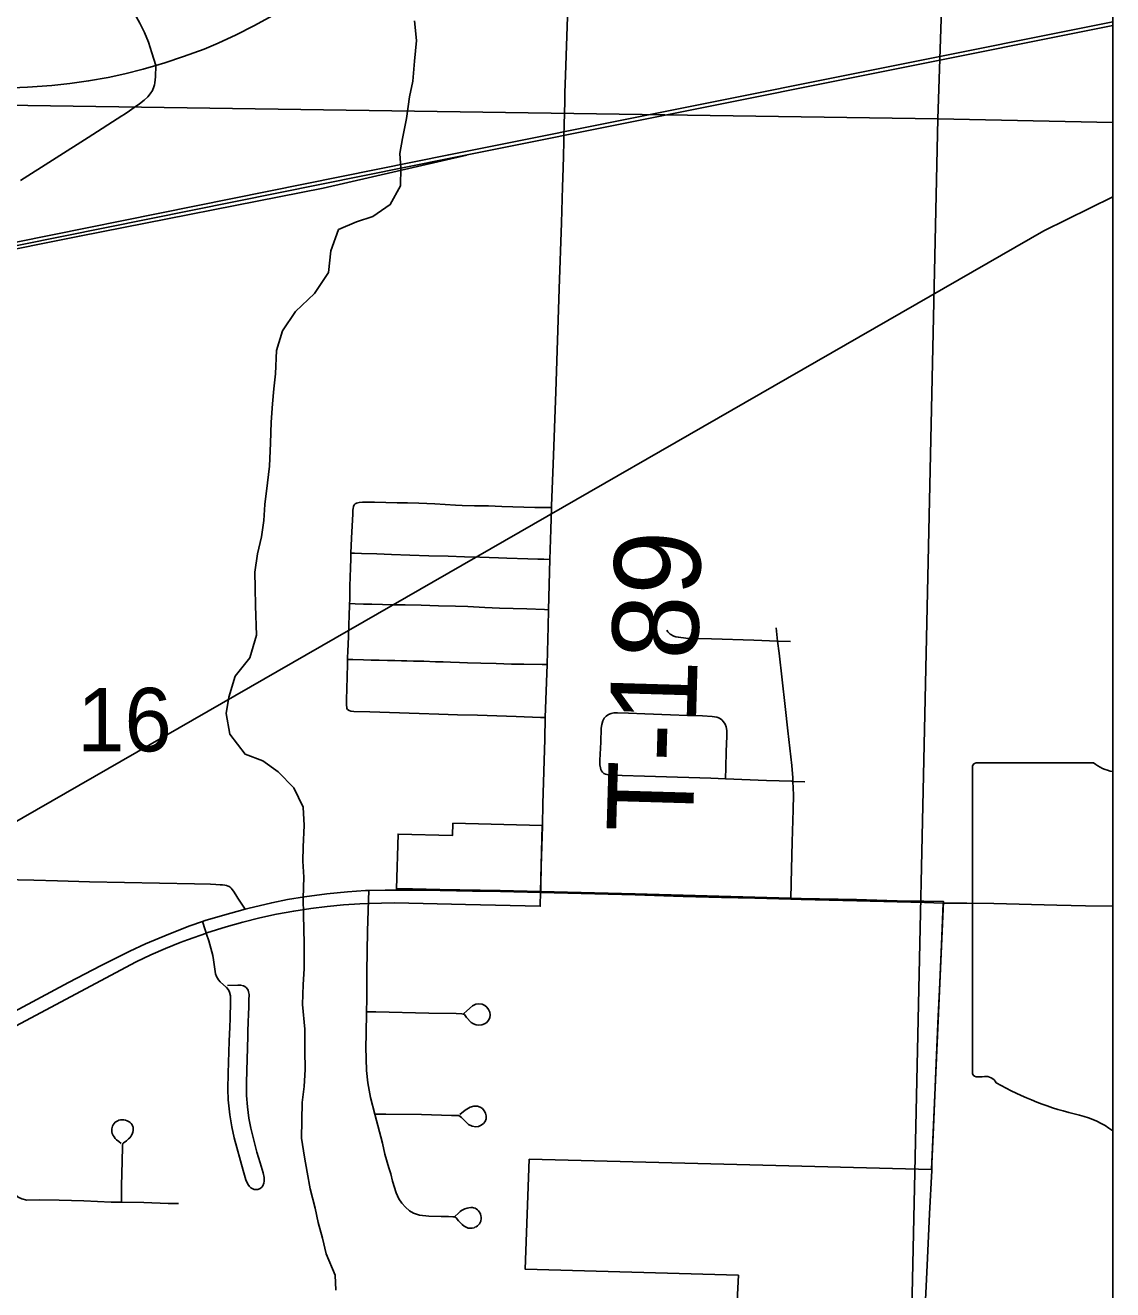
# Model space of a CAD drawing. Extents: x 0 to 34, y 0 to 22.
# Drawn here: x 8.183 to 8.9, y 17.76 to 18.594 of the extents above; entities that cross this region are included whole.
import ezdxf

# ---------------------------------------------------------------- set-up
doc = ezdxf.new("R2010")
doc.units = 0
for name, color, linetype in [('GM_X_City_Street', 7, 'Continuous'), ('GM_X_Corporation', 7, 'Continuous'), ('GM_X_County_Road', 7, 'Continuous'), ('GM_X_Minor_River', 7, 'Continuous'), ('GM_X_Rail_Line', 7, 'Continuous'), ('GM_X_Section_Text', 7, 'Continuous'), ('GM_X_State_Route', 7, 'Continuous'), ('GM_X_Township_Road', 7, 'Continuous'), ('GM_X_Township_Road_Text', 7, 'Continuous'), ('GM_X_Unincorporated_Text', 7, 'Continuous'), ('GM_X_US_Route', 7, 'Continuous'), ('SH_Data', 7, 'Continuous')]:
    doc.layers.add(name, color=color, linetype=linetype)

msp = doc.modelspace()

# ---------------------------------------------------------------- linework, layer by layer
at = {"layer": 'GM_X_City_Street'}
for points in [[(8.43372, 17.81455), (8.43131, 17.81714), (8.42944, 17.82018), (8.42776, 17.82405), (8.42532, 17.83165), (8.42423, 17.83647), (8.42276, 17.84056), (8.42023, 17.84949), (8.4186, 17.85682), (8.41367, 17.87598), (8.41085, 17.88694), (8.40894, 17.89662), (8.40809, 17.90457), (8.40758, 17.92002), (8.40779, 17.9287), (8.40809, 17.94344), (8.40827, 17.95169), (8.40844, 17.96973), (8.40881, 17.99644), (8.40945, 18.01691), (8.40965, 18.02327)], [(8.31658, 17.96078), (8.32323, 17.96098), (8.3251, 17.96093), (8.32693, 17.9605), (8.32802, 17.95993), (8.32895, 17.95917), (8.33004, 17.95769), (8.33043, 17.95654), (8.33072, 17.9547), (8.33061, 17.951), (8.33046, 17.94608), (8.33025, 17.94226), (8.33002, 17.93604), (8.32994, 17.93113), (8.32981, 17.92921), (8.32979, 17.92736), (8.32904, 17.89685), (8.32912, 17.88815), (8.3297, 17.88072), (8.33064, 17.87332), (8.33192, 17.8666), (8.33586, 17.85093), (8.338, 17.84378), (8.34005, 17.83722), (8.34063, 17.83414), (8.34069, 17.83165), (8.34046, 17.83043), (8.33979, 17.82874), (8.33902, 17.82777), (8.33813, 17.82699), (8.33647, 17.82624), (8.33405, 17.82629), (8.33189, 17.82743), (8.33103, 17.82829), (8.32993, 17.82982), (8.32866, 17.83269), (8.32685, 17.83869), (8.32088, 17.86027), (8.31931, 17.86756), (8.31809, 17.87555), (8.31704, 17.88544), (8.31678, 17.89227), (8.31702, 17.90284), (8.31755, 17.92397), (8.31812, 17.93328), (8.31833, 17.93887), (8.31856, 17.95008), (8.3184, 17.95381), (8.31786, 17.95621), (8.31708, 17.95788), (8.31594, 17.95933), (8.31174, 17.96306), (8.31054, 17.96448), (8.30927, 17.96659), (8.30867, 17.96834), (8.30732, 17.97764), (8.30675, 17.98053), (8.30547, 17.98539), (8.30408, 17.99024), (8.30268, 17.99456), (8.30176, 17.9974), (8.3, 18.00284)], [(8.40809, 17.94344), (8.41424, 17.94329), (8.44928, 17.94247), (8.4673, 17.94225), (8.47091, 17.94201), (8.47206, 17.94184), (8.47269, 17.9415), (8.47312, 17.94102), (8.47411, 17.93963), (8.47709, 17.9364), (8.47866, 17.93542), (8.48039, 17.93478), (8.48222, 17.93453), (8.48407, 17.9347), (8.48582, 17.93535), (8.48736, 17.93639), (8.48857, 17.9378), (8.48933, 17.93947), (8.48958, 17.9413), (8.48933, 17.94314), (8.48863, 17.94487), (8.48753, 17.94638), (8.48612, 17.9476), (8.48445, 17.94841), (8.48202, 17.9487), (8.4802, 17.94835), (8.47797, 17.94722), (8.47419, 17.9439), (8.47229, 17.94219)], [(8.41367, 17.87598), (8.42079, 17.8759), (8.44433, 17.87565), (8.46415, 17.87506), (8.46696, 17.8751), (8.46902, 17.87502), (8.47074, 17.87379), (8.47544, 17.86902), (8.47771, 17.86802), (8.48013, 17.8676), (8.48197, 17.86783), (8.48368, 17.86854), (8.48514, 17.86968), (8.48625, 17.87117), (8.48691, 17.87289), (8.48703, 17.87473), (8.48661, 17.87653), (8.48577, 17.87819), (8.48455, 17.87959), (8.48302, 17.88061), (8.48125, 17.88115), (8.47879, 17.88117), (8.4764, 17.88052), (8.47321, 17.8786), (8.46959, 17.8756)], [(8.24653, 17.81786), (8.24653, 17.82109), (8.24652, 17.8289), (8.24693, 17.83647), (8.24724, 17.85391), (8.24733, 17.85545), (8.2476, 17.85648), (8.24804, 17.85695), (8.249, 17.85771), (8.24983, 17.85838), (8.25126, 17.85958), (8.25201, 17.86029), (8.25283, 17.86124), (8.25328, 17.86204), (8.2536, 17.86272), (8.25406, 17.86411), (8.25427, 17.86514), (8.25431, 17.86625), (8.25423, 17.86729), (8.25397, 17.86823), (8.25359, 17.86895), (8.25299, 17.86971), (8.25224, 17.87035), (8.25167, 17.87077), (8.25027, 17.87159), (8.24926, 17.87189), (8.24813, 17.87209), (8.24704, 17.87217), (8.24591, 17.87209), (8.24493, 17.87192), (8.2441, 17.87159), (8.24326, 17.87113), (8.24254, 17.8706), (8.24179, 17.86978), (8.24116, 17.8689), (8.24074, 17.86798), (8.24045, 17.8672), (8.24026, 17.86619), (8.24025, 17.86521), (8.24032, 17.86431), (8.24057, 17.86322), (8.24112, 17.86194), (8.24172, 17.86088), (8.24253, 17.85992), (8.24335, 17.85909), (8.24482, 17.85786), (8.2465, 17.85662)], [(8.17665, 17.82278), (8.17846, 17.8213), (8.18093, 17.81999), (8.18414, 17.81933), (8.19243, 17.81935), (8.20548, 17.81916), (8.22177, 17.81868), (8.2397, 17.81796), (8.24653, 17.81786), (8.26142, 17.81765), (8.27735, 17.81711), (8.28412, 17.81701)], [(8.43372, 17.81455), (8.43639, 17.81228), (8.4391, 17.81063), (8.44299, 17.80932), (8.44916, 17.80857), (8.45726, 17.80838), (8.46224, 17.80836), (8.46502, 17.80831), (8.46593, 17.8083), (8.46667, 17.80807), (8.46733, 17.80749), (8.46886, 17.80551), (8.47109, 17.80327), (8.47255, 17.80203), (8.47418, 17.80115), (8.47512, 17.80085), (8.47598, 17.80073), (8.47783, 17.80082), (8.47899, 17.80109), (8.47962, 17.80137), (8.48048, 17.80174), (8.48122, 17.80233), (8.48251, 17.80366), (8.48338, 17.80531), (8.48373, 17.80713), (8.48375, 17.8081), (8.48359, 17.80899), (8.48335, 17.80994), (8.48297, 17.81075), (8.48241, 17.81163), (8.48192, 17.81228), (8.48131, 17.81286), (8.48047, 17.81343), (8.47967, 17.81386), (8.47875, 17.81414), (8.47788, 17.8143), (8.47691, 17.81437), (8.4756, 17.81425), (8.47445, 17.81403), (8.47287, 17.8134), (8.47158, 17.81283), (8.47071, 17.81234), (8.46989, 17.81176), (8.46865, 17.81067), (8.46644, 17.8085)]]:
    msp.add_lwpolyline(points, dxfattribs=at)
at = {"layer": 'GM_X_Corporation'}
for points in [[(8.9, 14.49422), (8.9, 20.89996), (2.1, 20.89996)], [(8.9, 14.49422), (8.9, 20.50415)], [(8.6425, 17.55961), (8.65329, 17.76979), (8.51264, 17.77379), (8.51539, 17.84616), (8.78059, 17.83951), (8.78854, 18.01597), (8.77547, 18.01629), (8.75791, 18.01656), (8.7312, 18.01732), (8.69467, 18.01802), (8.68782, 18.01822), (8.66408, 18.01894), (8.61684, 18.02016), (8.58516, 18.02109), (8.5229, 18.02261), (8.52397, 18.06619), (8.46513, 18.06759), (8.46488, 18.05964), (8.42888, 18.06053), (8.4278, 18.02432), (8.43847, 18.02433), (8.45651, 18.02403), (8.49629, 18.02326), (8.52288, 18.02261), (8.52268, 18.0129), (8.47331, 18.0141), (8.42679, 18.01515), (8.40929, 18.01482), (8.40363, 18.01459), (8.39285, 18.01384), (8.3821, 18.01279), (8.37139, 18.01144), (8.36011, 18.0097), (8.34889, 18.00762), (8.33774, 18.0052), (8.32666, 18.00246), (8.31567, 17.99939), (8.30282, 17.99536), (8.30261, 17.99528), (8.29012, 17.99088), (8.28526, 17.98903), (8.27557, 17.98512), (8.26599, 17.98095), (8.25627, 17.97639), (8.17353, 17.93211)]]:
    msp.add_lwpolyline(points, dxfattribs=at)
for points in [[(8.81843, 19.53953), (8.78463, 18.5318), (7.73457, 18.54715), (7.75042, 19.56547)], [(8.9, 18.52947), (8.9, 19.53779), (8.81843, 19.53953), (8.78463, 18.5318)], [(7.73457, 18.54715), (8.78463, 18.5318), (8.76248, 17.51563), (7.70158, 17.53728)], [(8.9, 17.51187), (8.9, 18.52947), (8.78463, 18.5318), (8.76248, 17.51563)]]:
    msp.add_lwpolyline(points, close=True, dxfattribs=at)
at = {"layer": 'GM_X_County_Road'}
msp.add_lwpolyline([(8.18012, 18.49132), (8.22474, 18.51963), (8.24677, 18.53378), (8.24833, 18.53481), (8.25193, 18.53724), (8.25498, 18.53935), (8.25859, 18.54182), (8.26162, 18.54413), (8.26395, 18.54635), (8.26559, 18.54836), (8.26695, 18.5506), (8.26795, 18.55302), (8.2683, 18.55429), (8.26854, 18.5556), (8.26896, 18.55958), (8.26935, 18.5671)], dxfattribs=at)
at = {"layer": 'GM_X_Minor_River'}
msp.add_lwpolyline([(8.38799, 17.75987), (8.38742, 17.76975), (8.38163, 17.7839), (8.37917, 17.79419), (8.37633, 17.8045), (8.37424, 17.81403), (8.37107, 17.82661), (8.36901, 17.83766), (8.36731, 17.84756), (8.36527, 17.86012), (8.36573, 17.88364), (8.36707, 17.89424), (8.36766, 17.90524), (8.36752, 17.91777), (8.36742, 17.93181), (8.36584, 17.94816), (8.36647, 17.96143), (8.36705, 17.97167), (8.36699, 17.98837), (8.3668, 17.99786), (8.3666, 18.00735), (8.36643, 18.01836), (8.3667, 18.03202), (8.36615, 18.04266), (8.36633, 18.05214), (8.36698, 18.06617), (8.36645, 18.07832), (8.36025, 18.09097), (8.34984, 18.10142), (8.33974, 18.10882), (8.32807, 18.11322), (8.31808, 18.12632), (8.31569, 18.14003), (8.31741, 18.15062), (8.32148, 18.16459), (8.33119, 18.17655), (8.33565, 18.19164), (8.33489, 18.21101), (8.33473, 18.22278), (8.33455, 18.23303), (8.3363, 18.24514), (8.3388, 18.25648), (8.34052, 18.26707), (8.3411, 18.27769), (8.3429, 18.29207), (8.34425, 18.30305), (8.34492, 18.31822), (8.34519, 18.33188), (8.34618, 18.34401), (8.34713, 18.35386), (8.34808, 18.36371), (8.34875, 18.37925), (8.35279, 18.39208), (8.36138, 18.40482), (8.37375, 18.41672), (8.38312, 18.43058), (8.38453, 18.44498), (8.38973, 18.45892), (8.40159, 18.464), (8.41227, 18.46759), (8.4238, 18.47534), (8.43049, 18.48773), (8.43071, 18.4995), (8.43014, 18.509), (8.43184, 18.51883), (8.43438, 18.53207), (8.43655, 18.54644), (8.43864, 18.55665), (8.43966, 18.56992), (8.44106, 18.58355), (8.43979, 18.59648)], dxfattribs=at)
at = {"layer": 'GM_X_Rail_Line'}
for points in [[(2.1, 17.25784), (2.18393, 17.27433), (2.73729, 17.38072), (3.32149, 17.49791), (3.96117, 17.62281), (4.55539, 17.74), (5.15654, 17.85642), (5.77541, 17.979), (6.33417, 18.09079), (6.90219, 18.20181), (7.3492, 18.28816), (7.42386, 18.30272), (8.00923, 18.41684), (8.46231, 18.50822), (8.9, 18.59581)], [(2.1, 17.25547), (2.18438, 17.27205), (2.73774, 17.37844), (3.32194, 17.49563), (3.96162, 17.62053), (4.55584, 17.73772), (5.15699, 17.85414), (5.77586, 17.97672), (6.33462, 18.08851), (6.90263, 18.19953), (7.34964, 18.28588), (7.42431, 18.30044), (8.00968, 18.41456), (8.46244, 18.50563), (8.9, 18.59339)], [(8.47427, 18.508), (8.37961, 18.48627), (8.21891, 18.45464), (8.02601, 18.41581), (8.00771, 18.41211)], [(7.41313, 17.80694), (7.67204, 17.79992), (7.72265, 17.8116), (7.77034, 17.83497), (8.85455, 18.45807), (8.9, 18.48042)]]:
    msp.add_lwpolyline(points, dxfattribs=at)
at = {"layer": 'GM_X_State_Route'}
for points in [[(8.32823, 18.01091), (8.32995, 18.01137), (8.34568, 18.0152), (8.35607, 18.01727), (8.36714, 18.01912), (8.38196, 18.02106), (8.3956, 18.02243), (8.40741, 18.0232), (8.40965, 18.02327)], [(8.40965, 18.02327), (8.42049, 18.02359), (8.42787, 18.0236)], [(8.42787, 18.0236), (8.43855, 18.02361), (8.45658, 18.02331), (8.478, 18.02289)], [(8.478, 18.02289), (8.49636, 18.02254), (8.52297, 18.02189)], [(8.52297, 18.02189), (8.58523, 18.02038), (8.61692, 18.01944), (8.64204, 18.0188)], [(8.64204, 18.0188), (8.66415, 18.01823), (8.6879, 18.0175)], [(8.6879, 18.0175), (8.69474, 18.0173), (8.73127, 18.0166), (8.75799, 18.01585), (8.77602, 18.01533), (8.78827, 18.01503)], [(8.3, 18.00284), (8.30177, 18.00344), (8.3131, 18.00687), (8.32823, 18.01091)], [(8.78827, 18.01503), (8.80379, 18.01506), (8.82161, 18.01472), (8.86311, 18.01357), (8.88207, 18.01325), (8.9, 18.01291)], [(8.16992, 17.94028), (8.21175, 17.96264), (8.2332, 17.97394), (8.25213, 17.98338), (8.26233, 17.98805), (8.27781, 17.99459), (8.29173, 18.00001), (8.3, 18.00284)]]:
    msp.add_lwpolyline(points, dxfattribs=at)
at = {"layer": 'GM_X_Township_Road'}
for p, q in [((8.52818, 18.20838), (8.52902, 18.24148)), ((8.67912, 18.18772), (8.67811, 18.19642)), ((8.67912, 18.18772), (8.68765, 18.18739)), ((8.52586, 18.13729), (8.52715, 18.17228)), ((8.68924, 18.09523), (8.69716, 18.09483))]:
    msp.add_line(p, q, dxfattribs=at)
for points in [[(8.53825, 18.5205), (8.53841, 18.52792), (8.53879, 18.54339), (8.53893, 18.54899), (8.5394, 18.56061), (8.54108, 18.61228), (8.54363, 18.69318), (8.54435, 18.71207), (8.54485, 18.72658)], [(8.26935, 18.5671), (8.26671, 18.57533), (8.26434, 18.5824), (8.26177, 18.58872), (8.25873, 18.59481), (8.25538, 18.60074), (8.25061, 18.60873), (8.24944, 18.61091), (8.24831, 18.61301)], [(8.53013, 18.27574), (8.53017, 18.27682), (8.53116, 18.30417), (8.5329, 18.35201), (8.53509, 18.41976), (8.53667, 18.46326), (8.53732, 18.48701), (8.53745, 18.49309), (8.53793, 18.50676), (8.53818, 18.51732), (8.53825, 18.5205)], [(8.39783, 18.24571), (8.39819, 18.25553), (8.39908, 18.27164), (8.39921, 18.2739), (8.39929, 18.275), (8.39944, 18.2764), (8.39989, 18.27746)], [(8.39989, 18.27746), (8.40067, 18.27817), (8.40159, 18.27861), (8.40248, 18.27882), (8.40332, 18.27895), (8.40549, 18.27916), (8.40725, 18.27924), (8.41337, 18.27926), (8.42839, 18.2789), (8.43522, 18.27882), (8.44267, 18.27855), (8.45322, 18.27804), (8.46686, 18.27727), (8.4712, 18.27702), (8.47926, 18.27691), (8.48858, 18.27676), (8.49728, 18.27644), (8.519, 18.2758), (8.52459, 18.27576), (8.53013, 18.27574)], [(8.52902, 18.24148), (8.52952, 18.26129), (8.53013, 18.27574)], [(8.39698, 18.21237), (8.39703, 18.21475), (8.39711, 18.21905), (8.39723, 18.22397), (8.39744, 18.23013), (8.39761, 18.2357), (8.3977, 18.24216), (8.39783, 18.24571)], [(8.39783, 18.24571), (8.40015, 18.24562), (8.40479, 18.24544), (8.41489, 18.24517), (8.42453, 18.24482), (8.43672, 18.24437), (8.44919, 18.24393), (8.46184, 18.24358), (8.47266, 18.24322), (8.48286, 18.24296), (8.49505, 18.24253), (8.50063, 18.24232), (8.51452, 18.24189), (8.52116, 18.24171), (8.52507, 18.24163), (8.52902, 18.24148)], [(8.39568, 18.17552), (8.39588, 18.18211), (8.39599, 18.18451), (8.39621, 18.19184), (8.39695, 18.21103), (8.39698, 18.21237)], [(8.39698, 18.21237), (8.40056, 18.2122), (8.40609, 18.21206), (8.41173, 18.21197), (8.41865, 18.21179), (8.42575, 18.21161), (8.43357, 18.21153), (8.44421, 18.21127), (8.4555, 18.211), (8.46677, 18.21064), (8.47488, 18.21038), (8.48607, 18.20984), (8.49571, 18.20948), (8.5049, 18.20922), (8.51373, 18.20886), (8.52543, 18.20845), (8.52818, 18.20838)], [(8.52715, 18.17228), (8.52744, 18.18049), (8.5279, 18.19728), (8.52818, 18.20838)], [(8.60605, 18.1948), (8.6068, 18.19381), (8.60764, 18.19287), (8.60835, 18.19224), (8.60909, 18.19172), (8.60984, 18.1913), (8.61075, 18.19092), (8.61202, 18.19056), (8.61375, 18.1902), (8.61868, 18.1897), (8.62366, 18.18946), (8.63547, 18.18921), (8.66344, 18.18834), (8.67912, 18.18772)], [(8.68924, 18.09523), (8.68916, 18.09763), (8.68855, 18.10568), (8.68593, 18.12852), (8.68413, 18.14457), (8.68005, 18.17975), (8.67912, 18.18772)], [(8.39661, 18.14192), (8.39555, 18.14266), (8.39517, 18.14335), (8.39505, 18.14405), (8.39498, 18.14518), (8.39497, 18.14688), (8.39499, 18.14809), (8.39504, 18.15059), (8.39511, 18.15487), (8.39515, 18.15676), (8.39525, 18.15921), (8.39527, 18.1611), (8.39568, 18.17552)], [(8.39568, 18.17552), (8.39918, 18.17544), (8.40604, 18.1753), (8.41125, 18.17517), (8.4164, 18.17502), (8.42187, 18.17492), (8.42689, 18.17486), (8.43113, 18.17474), (8.43478, 18.17467), (8.43915, 18.17454), (8.4458, 18.17435), (8.45349, 18.1741), (8.45857, 18.17391), (8.46339, 18.17372), (8.46946, 18.17358), (8.47461, 18.17333), (8.48348, 18.17308), (8.49358, 18.17283), (8.50362, 18.17257), (8.51183, 18.17252), (8.52382, 18.17233), (8.52715, 18.17228)], [(8.39661, 18.14192), (8.39778, 18.14159), (8.3998, 18.14134), (8.41041, 18.14102), (8.44273, 18.14001), (8.45578, 18.1395), (8.46821, 18.13917), (8.48126, 18.13875), (8.50675, 18.13795), (8.52287, 18.13739), (8.52586, 18.13729)], [(8.52407, 18.06647), (8.52443, 18.08043), (8.52563, 18.12309), (8.52586, 18.13729)], [(8.56453, 18.10043), (8.56365, 18.10128), (8.56307, 18.10209), (8.56265, 18.10315), (8.56237, 18.1042), (8.56202, 18.10603), (8.56197, 18.10749), (8.56199, 18.10914), (8.56248, 18.12098), (8.56288, 18.13032), (8.56322, 18.13279), (8.56396, 18.13516), (8.56485, 18.1368), (8.56606, 18.13821), (8.5676, 18.13927), (8.56932, 18.13999), (8.57115, 18.14033), (8.57364, 18.14031), (8.5809, 18.14009), (8.59169, 18.13981), (8.60849, 18.13918), (8.61969, 18.13872), (8.62957, 18.13837), (8.63586, 18.13799), (8.63894, 18.13745), (8.6407, 18.13684), (8.64226, 18.13584), (8.64354, 18.13449), (8.64452, 18.1329), (8.64518, 18.13116), (8.6456, 18.1287), (8.64561, 18.12496), (8.64518, 18.11501), (8.64493, 18.10443), (8.64475, 18.09695)], [(8.56453, 18.10043), (8.56556, 18.10002), (8.56671, 18.09971), (8.56793, 18.09946), (8.56947, 18.09928), (8.59861, 18.09841), (8.63519, 18.09739), (8.64475, 18.09695)], [(8.64475, 18.09695), (8.67175, 18.09569), (8.68849, 18.09527), (8.68924, 18.09523)], [(8.6879, 18.0175), (8.68809, 18.0284), (8.6888, 18.05528), (8.68939, 18.07652), (8.6895, 18.08645), (8.68924, 18.09523)], [(8.52297, 18.02189), (8.52307, 18.02635), (8.52336, 18.03935), (8.52404, 18.06547), (8.52407, 18.06647)], [(8.13717, 18.03115), (8.18892, 18.03004), (8.20447, 18.02958), (8.22563, 18.02899), (8.29475, 18.02761), (8.30537, 18.02741), (8.30891, 18.0273), (8.31161, 18.02714), (8.31321, 18.02699), (8.31475, 18.02678), (8.31592, 18.02656), (8.31687, 18.02625), (8.31751, 18.02598), (8.3182, 18.02556), (8.31894, 18.02487), (8.31958, 18.02407), (8.32043, 18.0228), (8.32197, 18.02046), (8.32337, 18.01832), (8.32823, 18.01091)], [(8.78066, 17.83879), (8.78084, 17.84347), (8.78185, 17.86704), (8.78379, 17.91493), (8.78503, 17.94042), (8.7858, 17.95784), (8.78706, 17.9877), (8.78827, 18.01503)], [(8.76613, 17.515), (8.76788, 17.55955), (8.76915, 17.58996), (8.77032, 17.61539), (8.77208, 17.65138), (8.77428, 17.706), (8.77568, 17.73515), (8.77795, 17.78107), (8.77919, 17.81023), (8.78066, 17.83879)]]:
    msp.add_lwpolyline(points, dxfattribs=at)
at = {"layer": 'GM_X_Unincorporated_Text'}
for p, q in [((8.80755, 18.104), (8.80755, 17.90392)), ((8.88736, 18.10747), (8.81009, 18.10747)), ((8.9, 17.86502), (8.9, 18.10164))]:
    msp.add_line(p, q, dxfattribs=at)
for centre, radius, start, end in [((8.81057, 18.10445), 0.00305, 98.97798, 188.59666), ((8.90575, 18.1307), 0.02963, 231.64044, 258.81024), ((8.8106, 17.90347), 0.00308, 171.49107, 258.30654), ((8.81106, 17.92394), 0.02352, 267.33899, 280.60386), ((8.81588, 17.89236), 0.00848, 29.74838, 93.27175), ((8.92294, 18.07216), 0.20192, 240.41292, 257.1985), ((8.86274, 17.814), 0.06318, 53.85417, 75.83597)]:
    msp.add_arc(centre, radius, start, end, dxfattribs=at)
at = {"layer": 'GM_X_US_Route'}
msp.add_lwpolyline([(8.1697, 18.55217), (8.18464, 18.55274), (8.20078, 18.55387), (8.21257, 18.55506), (8.22491, 18.55681), (8.23779, 18.55913), (8.24875, 18.56148), (8.26083, 18.56458), (8.26935, 18.5671), (8.27516, 18.56882), (8.28759, 18.57291), (8.30104, 18.57787), (8.31027, 18.58166), (8.32213, 18.58721), (8.33379, 18.59313), (8.35126, 18.60269)], dxfattribs=at)
at = {"layer": 'SH_Data'}
msp.add_line((8.9, 20.89996), (8.9, 14.09996), dxfattribs=at)

# ---------------------------------------------------------------- texts
at = {"layer": 'GM_X_Section_Text'}
msp.add_text('16', height=0.041856, rotation=0.00001, dxfattribs=at).set_placement((8.21747, 18.11499))
at = {"layer": 'GM_X_Township_Road_Text'}
msp.add_text('T-189', height=0.056818, rotation=88.34671, dxfattribs=at).set_placement((8.62314, 18.06105))

doc.saveas('drawing.dxf')
